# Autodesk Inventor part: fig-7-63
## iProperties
Shininess: 64.0
Length Units: 11269
Angle Units: 11279
Time Units: 11290
Mass Units: 11283
Length Display Precision: 3
Angle Display Precision: 2
Compacted: True
Part Number: fig-7-63
Document SubType Name: Modeling
Created: 2002-12
Designer: deepak
Density: 0.0
Volumn: 0.0
Area: 0.0
PropertySet Name: Model Information
Control State: 0
Master: False
Checked Out: False
Author: deepak
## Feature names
1. Extrusion1
2. Split1
